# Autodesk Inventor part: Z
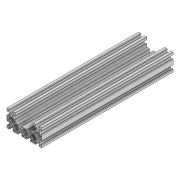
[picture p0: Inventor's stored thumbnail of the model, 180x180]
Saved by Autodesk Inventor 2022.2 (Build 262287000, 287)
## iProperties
Created: 2024-09
Part Number: Z
Material: Generico
Document SubType Name: Modeling
Designer: 18907419
Density: 1 g/cm^3
Appearance: Default
Author: 18907419
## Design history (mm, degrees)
sketch "Schizzo1"
  geometry: L1 (29.79, -3.9)-(30, -3.69); L2 (30, -3.69)-(30.21, -3.9); L3 (30.21, -3.9)-(32.839, -3.9); L4 (32.839, -3.9)-(35.5, -6.561); L5 (35.5, -6.561)-(35.5, -8.2); L6 (35.5, -8.2)-(33.395, -8.2); L7 (33.395, -8.2)-(33.395, -8.815); L8 (33.395, -8.815)-(34.58, -10); L9 (34.58, -10)-(39.5, -10); L10 (40, -9.5)-(40, -4.58); L11 (40, -4.58)-(38.815, -3.395); L12 (38.815, -3.395)-(38.2, -3.395); L13 (38.2, -3.395)-(38.2, -5.5); L14 (38.2, -5.5)-(36.561, -5.5); L15 (36.561, -5.5)-(33.9, -2.839); L16 (33.9, -2.839)-(33.9, -0.21); L17 (33.9, -0.21)-(33.69, 0); L18 (33.69, 0)-(33.9, 0.21); L19 (33.9, 0.21)-(33.9, 2.839); L20 (33.9, 2.839)-(36.561, 5.5); L21 (36.561, 5.5)-(38.2, 5.5); L22 (38.2, 5.5)-(38.2, 3.395); L23 (38.2, 3.395)-(38.815, 3.395); L24 (38.815, 3.395)-(40, 4.58); L25 (40, 4.58)-(40, 15.42); L26 (40, 15.42)-(38.815, 16.605); L27 (38.815, 16.605)-(38.2, 16.605); L28 (38.2, 16.605)-(38.2, 14.5); L29 (38.2, 14.5)-(36.561, 14.5); L30 (36.561, 14.5)-(33.9, 17.161); L31 (33.9, 17.161)-(33.9, 19.79); L32 (33.9, 19.79)-(33.69, 20); L33 (33.69, 20)-(33.9, 20.21); L34 (33.9, 20.21)-(33.9, 22.839); L35 (33.9, 22.839)-(36.561, 25.5); L36 (36.561, 25.5)-(38.2, 25.5); L37 (38.2, 25.5)-(38.2, 23.395); L38 (38.2, 23.395)-(38.815, 23.395); L39 (38.815, 23.395)-(40, 24.58); L40 (40, 24.58)-(40, 29.5); L41 (39.5, 30)-(34.58, 30); L42 (34.58, 30)-(33.395, 28.815); L43 (33.395, 28.815)-(33.395, 28.2); L44 (33.395, 28.2)-(35.5, 28.2); L45 (35.5, 28.2)-(35.5, 26.561); L46 (35.5, 26.561)-(32.839, 23.9); L47 (32.839, 23.9)-(30.21, 23.9); L48 (30.21, 23.9)-(30, 23.69); L49 (30, 23.69)-(29.79, 23.9); L50 (29.79, 23.9)-(27.161, 23.9); L51 (27.161, 23.9)-(24.5, 26.561); L52 (24.5, 26.561)-(24.5, 28.2); L53 (24.5, 28.2)-(26.605, 28.2); L54 (26.605, 28.2)-(26.605, 28.815); L55 (26.605, 28.815)-(25.42, 30); L56 (25.42, 30)-(20.5, 30); L57 (20, 29.5)-(20, 24.58); L58 (20, 24.58)-(21.185, 23.395); L59 (21.185, 23.395)-(21.8, 23.395); L60 (21.8, 23.395)-(21.8, 25.5); L61 (21.8, 25.5)-(23.439, 25.5); L62 (23.439, 25.5)-(26.1, 22.839); L63 (26.1, 22.839)-(26.1, 20.21); L64 (26.1, 20.21)-(26.31, 20)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; C1 r 2.3 at (-30, 0); C2 r 2.3 at (-30, 20); C3 r 2.3 at (-10, 0); C4 r 2.3 at (10, 0); C5 r 2.3 at (30, 0); C6 r 2.3 at (30, 20); A1 r 0.5 centre (39.5, -9.5) between (39.5, -10) and (40, -9.5); A2 r 0.5 centre (39.5, 29.5) between (40, 29.5) and (39.5, 30); A3 r 0.5 centre (20.5, 29.5) between (20.5, 30) and (20, 29.5); A4 r 0.5 centre (-20.5, 29.5) between (-20, 29.5) and (-20.5, 30); A5 r 0.5 centre (-39.5, 29.5) between (-39.5, 30) and (-40, 29.5); A6 r 0.5 centre (-39.5, -9.5) between (-40, -9.5) and (-39.5, -10); 311 further points
  constraints: 608 end point, 12 centre point, 12 point on circle
extrude "Estrusione1" new body sketch "Schizzo1" distance "d0" = 300; taper "d1" = 0 deg
node "Solido1"
